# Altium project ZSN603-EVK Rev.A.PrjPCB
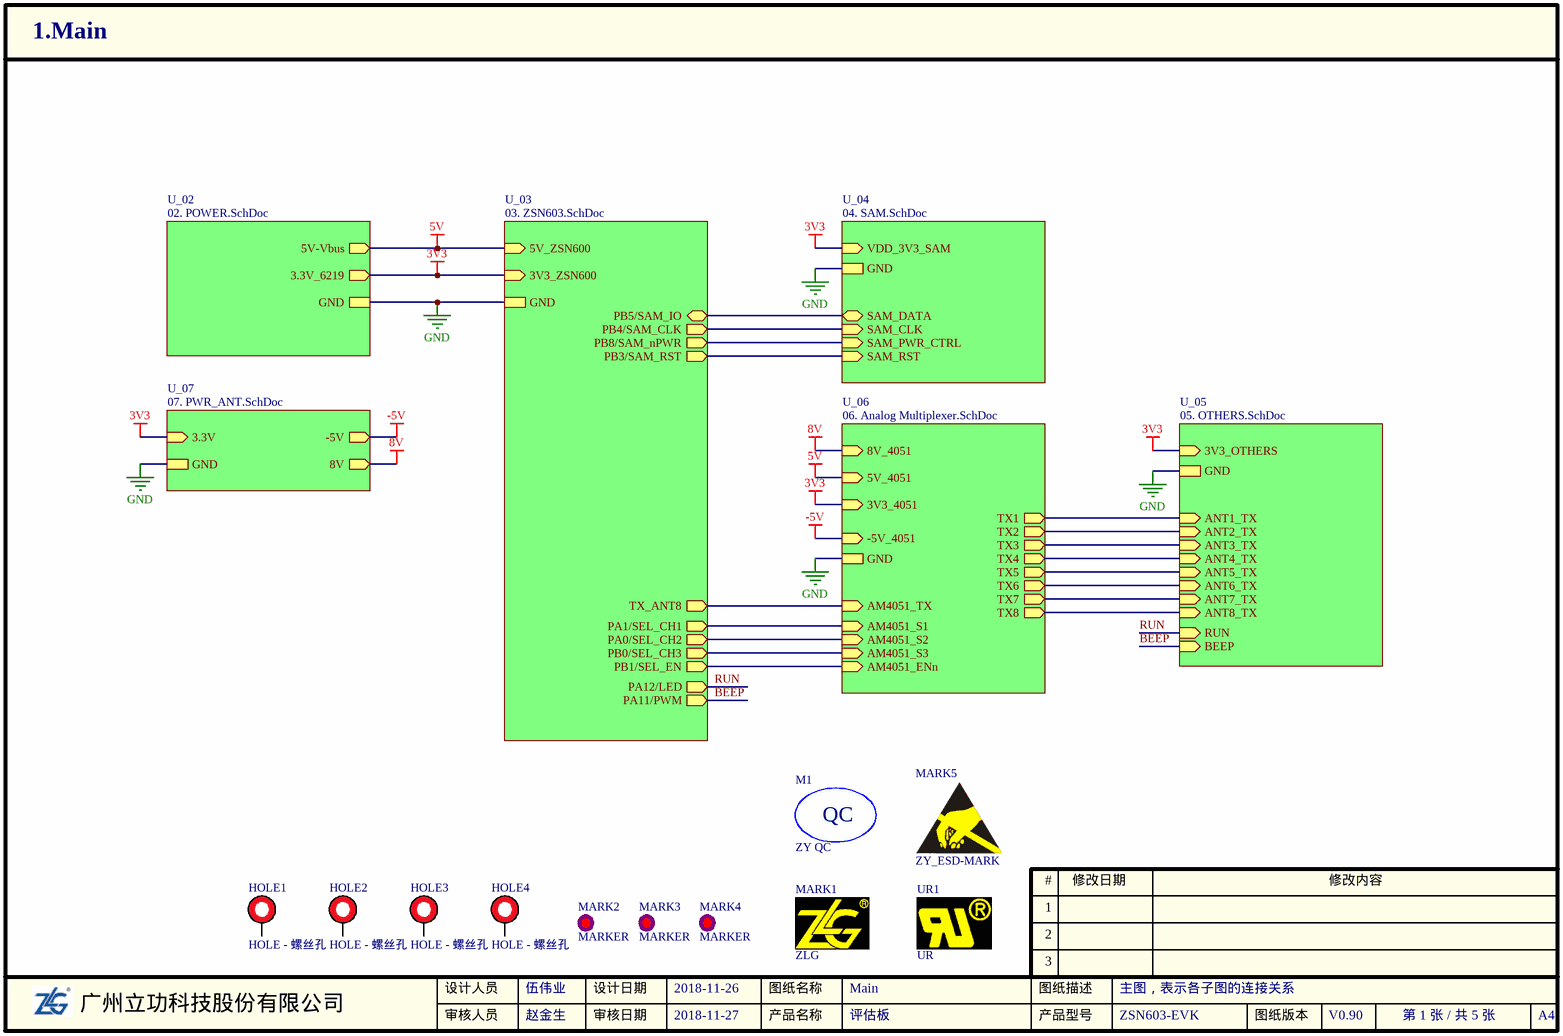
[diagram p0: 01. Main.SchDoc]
productName: 评估板; productModel: ZSN603-EVK
7 sheets, 139 parts. Net scope: hierarchical (ports join the sheet entries above them; power ports are global).
Board file: ZSN603-EVK Rev.A.PcbDoc
Sheets:
  01. Main.SchDoc
    U_02 = 02. POWER.SchDoc
    U_03 = 03. ZSN603.SchDoc
    U_04 = 04. SAM.SchDoc
    U_05 = 05. OTHERS.SchDoc
    U_06 = 06. Analog Multiplexer.SchDoc
    U_07 = 07. PWR_ANT.SchDoc

## Sheet 01. Main.SchDoc
size A4; CheckedBy: 赵金生; Author: 伍伟业; CompanyName: 广州周立功单片机科技有限公司; DocumentNumber: 1; SheetNumber: 1; SheetTotal: 5; PageSetup: Record=PageOptions¦CenterHorizontal=True¦CenterVertical=True¦PrintScale=1.00¦XCorrection=1.00¦YCorrection=1.00¦PrintKind=0¦BorderSize=5000000¦LeftOffset=0¦BottomOffset=0¦Orientation=2¦PaperLength=1000¦PaperWidth=1000¦Scale=100¦PaperSource=7¦PrintQuality=600¦MediaType=1¦DitherType=10¦PaperKind=A4¦PrintScaleMode=1; DesignDate: 2018-11-26; CheckDate: 2018-11-27; SheetName: Main; SheetVersion: V0.90; SheetDescription: 主图，表示各子图的连接关系

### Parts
HOLE1  HOLE - 螺丝孔  [HOLE-3.2 - Screw]  (no BOM)
HOLE2  HOLE - 螺丝孔  [HOLE-3.2 - Screw]  (no BOM)
HOLE3  HOLE - 螺丝孔  [HOLE-3.2 - Screw]  (no BOM)
HOLE4  HOLE - 螺丝孔  [HOLE-3.2 - Screw]  (no BOM)
M1  ZY QC  [ZY_QC]  (no BOM)
MARK1  ZLG  [ZLG1.0]  (no BOM)
MARK2  MARKER  [MARKER-C-1.0M]  (no BOM)
MARK3  MARKER  [MARKER-C-1.0M]  (no BOM)
MARK4  MARKER  [MARKER-C-1.0M]  (no BOM)
MARK5  ZY_ESD-MARK  [ZY_ESD-7]  (no BOM)
UR1  UR  [ZY_UR-3X2]  (no BOM)

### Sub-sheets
U_02 = 02. POWER.SchDoc: GND, 3.3V_6219 (out), 5V-Vbus (out)
U_03 = 03. ZSN603.SchDoc: GND, 3V3_ZSN600 (in), 5V_ZSN600 (in), PB3/SAM_RST (out), PB4/SAM_CLK (out), PB5/SAM_IO (bidir), PB8/SAM_nPWR (out), PA1/SEL_CH1 (out), PA0/SEL_CH2 (out), PB0/SEL_CH3 (out), PB1/SEL_EN (out), PA12/LED (out), PA11/PWM (out), TX_ANT8 (out)
U_04 = 04. SAM.SchDoc: SAM_CLK (in), SAM_DATA (bidir), SAM_RST (in), SAM_PWR_CTRL (in), VDD_3V3_SAM (in), GND
U_05 = 05. OTHERS.SchDoc: GND, 3V3_OTHERS (in), RUN (in), BEEP (in), ANT1_TX (in), ANT2_TX (in), ANT3_TX (in), ANT4_TX (in), ANT5_TX (in), ANT6_TX (in), ANT7_TX (in), ANT8_TX (in)
U_06 = 06. Analog Multiplexer.SchDoc: AM4051_S2 (in), AM4051_S1 (in), AM4051_S3 (in), GND, 8V_4051 (in), -5V_4051 (in), AM4051_ENn (in), AM4051_TX (in), TX1 (out), TX2 (out), TX3 (out), TX4 (out), TX5 (out), TX6 (out), TX7 (out), TX8 (out), 3V3_4051 (in), 5V_4051 (in)
U_07 = 07. PWR_ANT.SchDoc: -5V (out), 3.3V (in), GND, 8V (out)

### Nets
3V3: sheet U_02/3.3V_6219, sheet U_03/3V3_ZSN600, sheet U_04/VDD_3V3_SAM, sheet U_05/3V3_OTHERS, sheet U_06/3V3_4051, sheet U_07/3.3V  [project net 3.3V]
5V: sheet U_02/5V-Vbus, sheet U_03/5V_ZSN600, sheet U_06/5V_4051
8V: sheet U_06/8V_4051, sheet U_07/8V
-5V: sheet U_06/-5V_4051, sheet U_07/-5V
GND: sheet U_02/GND, sheet U_03/GND, sheet U_04/GND, sheet U_05/GND, sheet U_06/GND, sheet U_07/GND
AM4051_ENn: sheet U_03/PB1/SEL_EN, sheet U_06/AM4051_ENn
AM4051_S1: sheet U_03/PA1/SEL_CH1, sheet U_06/AM4051_S1
AM4051_S2: sheet U_03/PA0/SEL_CH2, sheet U_06/AM4051_S2
AM4051_S3: sheet U_03/PB0/SEL_CH3, sheet U_06/AM4051_S3
AM4051_TX: sheet U_03/TX_ANT8, sheet U_06/AM4051_TX
ANT1_TX: sheet U_05/ANT1_TX, sheet U_06/TX1
ANT2_TX: sheet U_05/ANT2_TX, sheet U_06/TX2
ANT3_TX: sheet U_05/ANT3_TX, sheet U_06/TX3
ANT4_TX: sheet U_05/ANT4_TX, sheet U_06/TX4
ANT5_TX: sheet U_05/ANT5_TX, sheet U_06/TX5
ANT6_TX: sheet U_05/ANT6_TX, sheet U_06/TX6
ANT7_TX: sheet U_05/ANT7_TX, sheet U_06/TX7
ANT8_TX: sheet U_05/ANT8_TX, sheet U_06/TX8
BEEP: sheet U_03/PA11/PWM, sheet U_05/BEEP
PB3/SAM_RST: sheet U_03/PB3/SAM_RST, sheet U_04/SAM_RST
PB4/SAM_CLK: sheet U_03/PB4/SAM_CLK, sheet U_04/SAM_CLK
PB5/SAM_IO: sheet U_03/PB5/SAM_IO, sheet U_04/SAM_DATA
PB8/SAM_nPWR: sheet U_03/PB8/SAM_nPWR, sheet U_04/SAM_PWR_CTRL
RUN: sheet U_03/PA12/LED, sheet U_05/RUN  [project net PA12/LED]

Not connected (* = marked no-connect by the designer): HOLE1 1; HOLE2 1; HOLE3 1; HOLE4 1; MARK2 0; MARK3 0; MARK4 0

## Sheet 02. POWER.SchDoc
size A4; CheckedBy: 赵金生; Author: 伍伟业; CompanyName: 广州周立功单片机科技有限公司; DocumentNumber: 2; SheetNumber: 2; SheetTotal: 5; PageSetup: Record=PageOptions|CenterHorizontal=True|CenterVertical=True|PrintScale=1.00|XCorrection=1.00|YCorrection=1.00|PrintKind=0|BorderSize=5000000|LeftOffset=0|BottomOffset=0|Orientation=2|PaperLength=1000|PaperWidth=1000|Scale=100|PaperSource=7|PrintQuality=600|MediaType=1|DitherType=10|PaperKind=A4|PrintScaleMode=1; DesignDate: 2018-11-26; CheckDate: 2018-11-27; SheetName: POWER; SheetVersion: V0.90; SheetDescription: 评估板电源
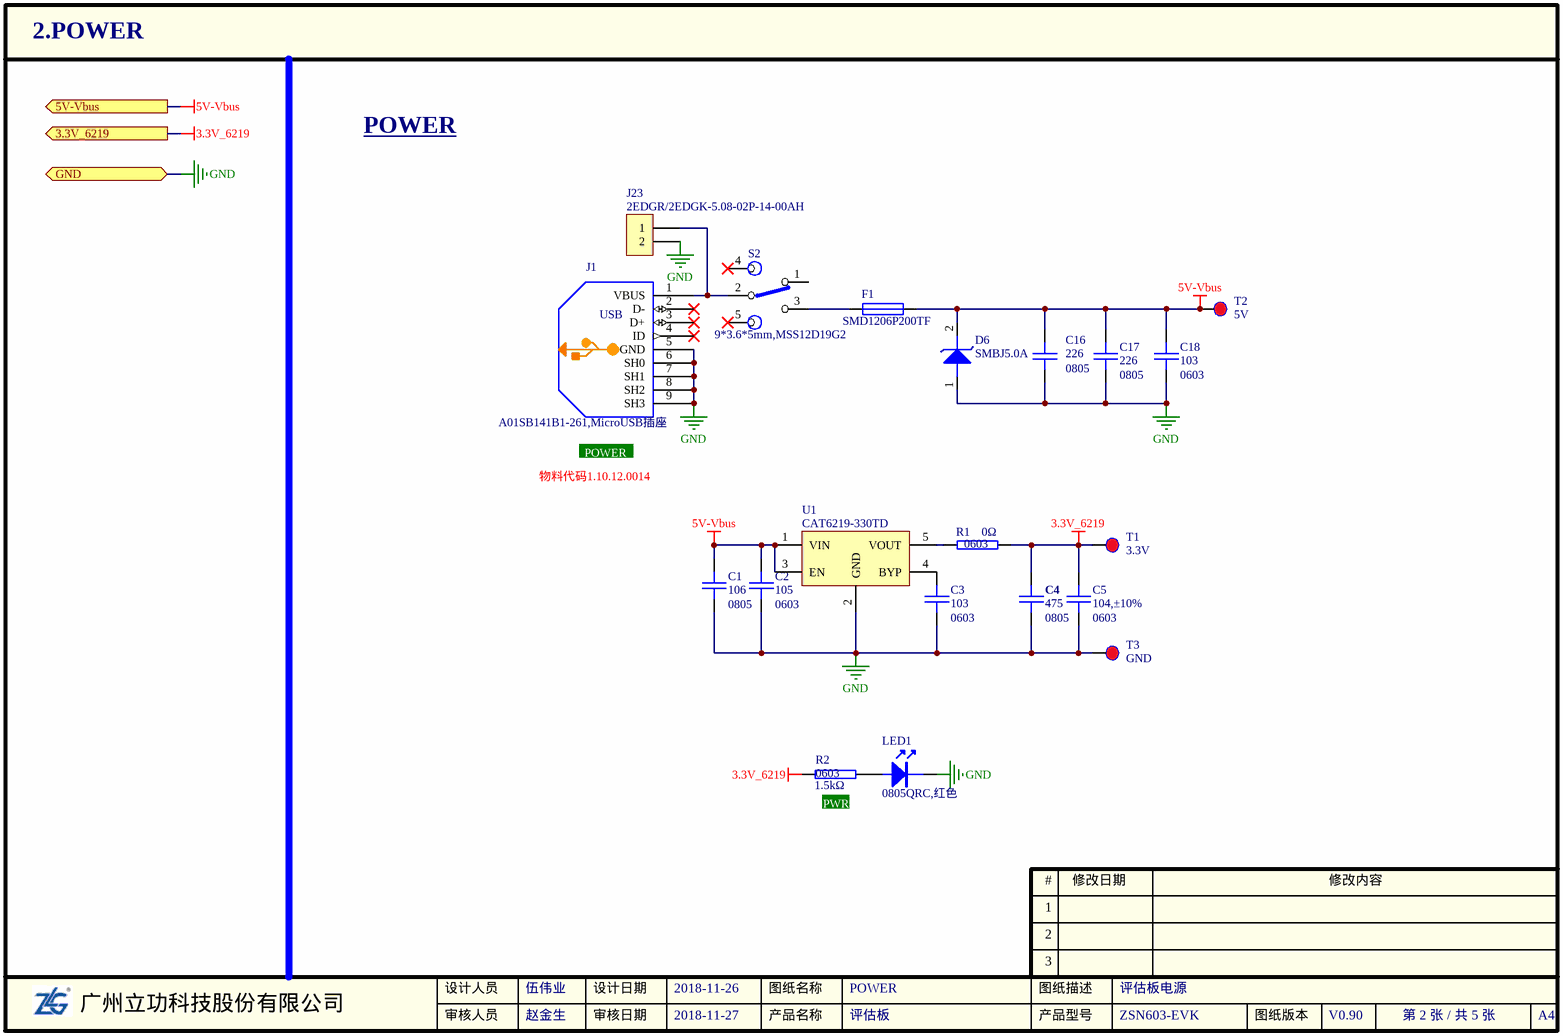
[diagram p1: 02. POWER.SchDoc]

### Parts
C1  封装: 0805  [0805C]  (hidden comment: 106)
C2  封装: 0603  [0603C]  (hidden comment: 105)
C3  封装: 0603  [0603C]  (hidden comment: 103)
C4  封装: 0805  [0805C]  (hidden comment: 475)
C5  封装: 0603  [0603C]  (hidden comment: 104,±10%)
C16  封装: 0805  [0805C]  (hidden comment: 226)
C17  封装: 0805  [0805C]  (hidden comment: 226)
C18  封装: 0603  [0603C]  (hidden comment: 103)
D6  SMBJ5.0A  [SOD-1812D]
F1  SMD1206P200TF  [FUSE320X165X160]
J1  A01SB141B1-261,MicroUSB插座  [MICROUSB-5S]
J23  2EDGR/2EDGK-5.08-02P-14-00AH  [CON508P1210W160D445S-2RA]
LED1  0805QRC,红色  [LED-0805]
R1  封装: 0603  [0603R]  (hidden comment: 0Ω)
R2  封装: 0603  [0603R]  (hidden comment: 1.5kΩ)
S2  9*3.6*5mm,MSS12D19G2  [MSS12D19G2]
T1  3.3V  [PAD-25/40]  (no BOM)
T2  5V  [PAD-25/40]  (no BOM)
T3  GND  [PAD-25/40]  (no BOM)
U1  CAT6219-330TD  [SOT-23-5]

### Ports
3.3V_6219 (out), 5V-Vbus (out), GND

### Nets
3.3V_6219: C4.1 C5.1 R1.2 R2.1 T1.1 ; port 3.3V_6219  [project net 3.3V]
5V-Vbus: C1.1 C2.1 C16.1 C17.1 C18.1 D6.2 F1.2 T2.1 U1.1(VIN) U1.3(EN) ; port 5V-Vbus  [project net 5V]
GND: C1.2 C2.2 C3.2 C4.2 C5.2 C16.2 C17.2 C18.2 D6.1 J1.5(GND) J1.6(SH0) J1.7(SH1) J1.8(SH2) J1.9(SH3) J23.2 LED1.2 T3.1 U1.2(GND) ; port GND
NetC3_1: C3.1 U1.4(BYP)
NetF1_1: F1.1 S2.3(NO)
NetJ1_1: J1.1(VBUS) J23.1 S2.2(COMMON)
NetLED1_1: LED1.1 R2.2
NetR1_1: R1.1 U1.5(VOUT)

Not connected (* = marked no-connect by the designer): J1 2(D-)* 3(D+)* 4(ID)*; S2 1(NC) 4(NO)* 5(NO)*

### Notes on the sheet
- POWER
- 物料代码1.10.12.0014
- (near J1) POWER
- (near R2) PWR

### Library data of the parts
C1 = 1.02.02.0055: 106,10μF,±10%,10V,X5R,0805,RoHS; 名称: 电容; 贴片和直插: SMT; 器件优选方案: 量产物料,优先选用; 设备封装名称: C0805_106_X5R_10V_10%
C2 = 1.02.01.0036: 105,1μF,±10%,16V,X7R,0603,*,RoHS; 名称: 电容; 设备封装名称: C0603_105_X7R_16V_10%; 厂商: TDK; 贴片和直插: SMT; 器件优选方案: 量产物料,不推荐使用
C3 = 1.02.01.0024: 103,±10%,50V,X7R,0603,*,RoHS; 名称: 电容; 设备封装名称: C0603_103_X7R_50V_10%; 厂商: muRata; 贴片和直插: SMT; 器件优选方案: 量产物料,不推荐使用
C4 = 1.02.02.0064: 475,±10%,16V,X7R,0805,RoHS; 名称: 电容; 设备封装名称: C0805_475_X7R_16V_10%; 贴片和直插: SMT; 器件优选方案: 优先选用
C5 = 1.02.01.0032: Capacitor; 名称: 电容; 设备封装名称: C0603_104_X7R_50V_10%; 厂商: muRata; 型号: 104,±10%,50V,X7R; 贴片和直插: SMT; 器件优选方案: 量产物料,优先选用
C16 C17 = 1.02.02.0059: GRM21BR60J226ME39L,226,22μF,±20%,6.3V,X5R,0805,muRata,RoHS; 名称: 电容; 设备封装名称: C0805_226_X5R_6.3V_20%; 贴片和直插: SMT; 器件优选方案: 正常状态，可以选用
C18 = 1.02.01.0024: GRM188R71H103KA01D,103,±10%,50V,X7R,0603,muRata,RoHS; 名称: 电容; 设备封装名称: C0603_103_X7R_50V_10%; 贴片和直插: SMT; 器件优选方案: 正常状态，可以选用
D6 = 1.04.03.0001: SMBJ5.0A,DO-214AA,君耀,RoHS; 名称: TVS瞬态抑制二极管; 设备封装名称: DO-214AA_SMBJ5.0A; 贴片和直插: SMT; 器件优选方案: 正常状态，可以选用
F1 = 1.06.03.0017: SMD1206P200TF,1206,Polytronics,RoHS; 名称: 保险丝; 封装: 1206; 贴片和直插: SMT; 器件优选方案: 临时/偏门物料/不主推物料，谨慎选用
J1 = 1.10.12.0014: A01SB141B1-261,MicroUSB插座,SMT,艾立信,RoHS; PCB备注: 141030lmd; 器件优选方案: 正常状态，可以选用
J23 = 1.10.06.0027: 2EDGR/2EDGK-5.08-02P-14-00AH,DEGSON,RoHS; 名称: 端子; 贴片和直插: THT; PCB备注: xhm-lq-wyy-150126; 器件优选方案: 正常状态，可以选用
LED1 = 1.04.05.0001: 0805QRC,红色,0805,RoHS; 名称: 发光二极管; 封装: 0805; 设备封装名称: LED0805-RED; 贴片和直插: SMT; 器件优选方案: 正常状态，可以选用
R1 = 1.01.01.0001: 名称: 电阻; 设备封装名称: R0603_0R; 厂商: Ralec; 贴片和直插: SMT; 器件优选方案: 状态正常
R2 = 1.01.01.0037: 1.5KΩ,0603,*,RoHS; 名称: 电阻; 设备封装名称: R0603_1.5K; 厂商: Ralec; 贴片和直插: SMT; 器件优选方案: 状态正常
S2 = 1.09.07.0029: 9*3.6*5mm,MSS12D19G2,东昇,RoHS; 名称: 拨动开关; 贴片和直插: THT; PCB备注: 170616 ZJY; 器件优选方案: 正常状态，可以选用
T1-T3 = TEST-DOT
U1 = 1.05.10.0321: CAT6219-330TD,TSOT-23-5,ON,RoHS; 名称: 集成电路; 设备封装名称: TSOT-23-5_CAT6219-330TD-GT3; 贴片和直插: SMT; 器件优选方案: 量产物料,优先选用

## Sheet 03. ZSN603.SchDoc
size A3; CheckedBy: 赵金生; Author: 伍伟业; CompanyName: 广州周立功单片机科技有限公司; DocumentNumber: 3; SheetNumber: 3; SheetTotal: 5; PageSetup: Record=PageOptions¦CenterHorizontal=True¦CenterVertical=True¦PrintScale=1.00¦XCorrection=1.00¦YCorrection=1.00¦PrintKind=0¦BorderSize=5000000¦LeftOffset=0¦BottomOffset=0¦Orientation=2¦PaperLength=1000¦PaperWidth=1000¦Scale=100¦PaperSource=7¦PrintQuality=600¦MediaType=1¦DitherType=10¦PaperKind=A4¦PrintScaleMode=1; DesignDate: 2018-11-26; CheckDate: 2018-11-27; SheetName: ZSN603; SheetVersion: V0.90; SheetDescription: ZSN603最小系统及信号端口
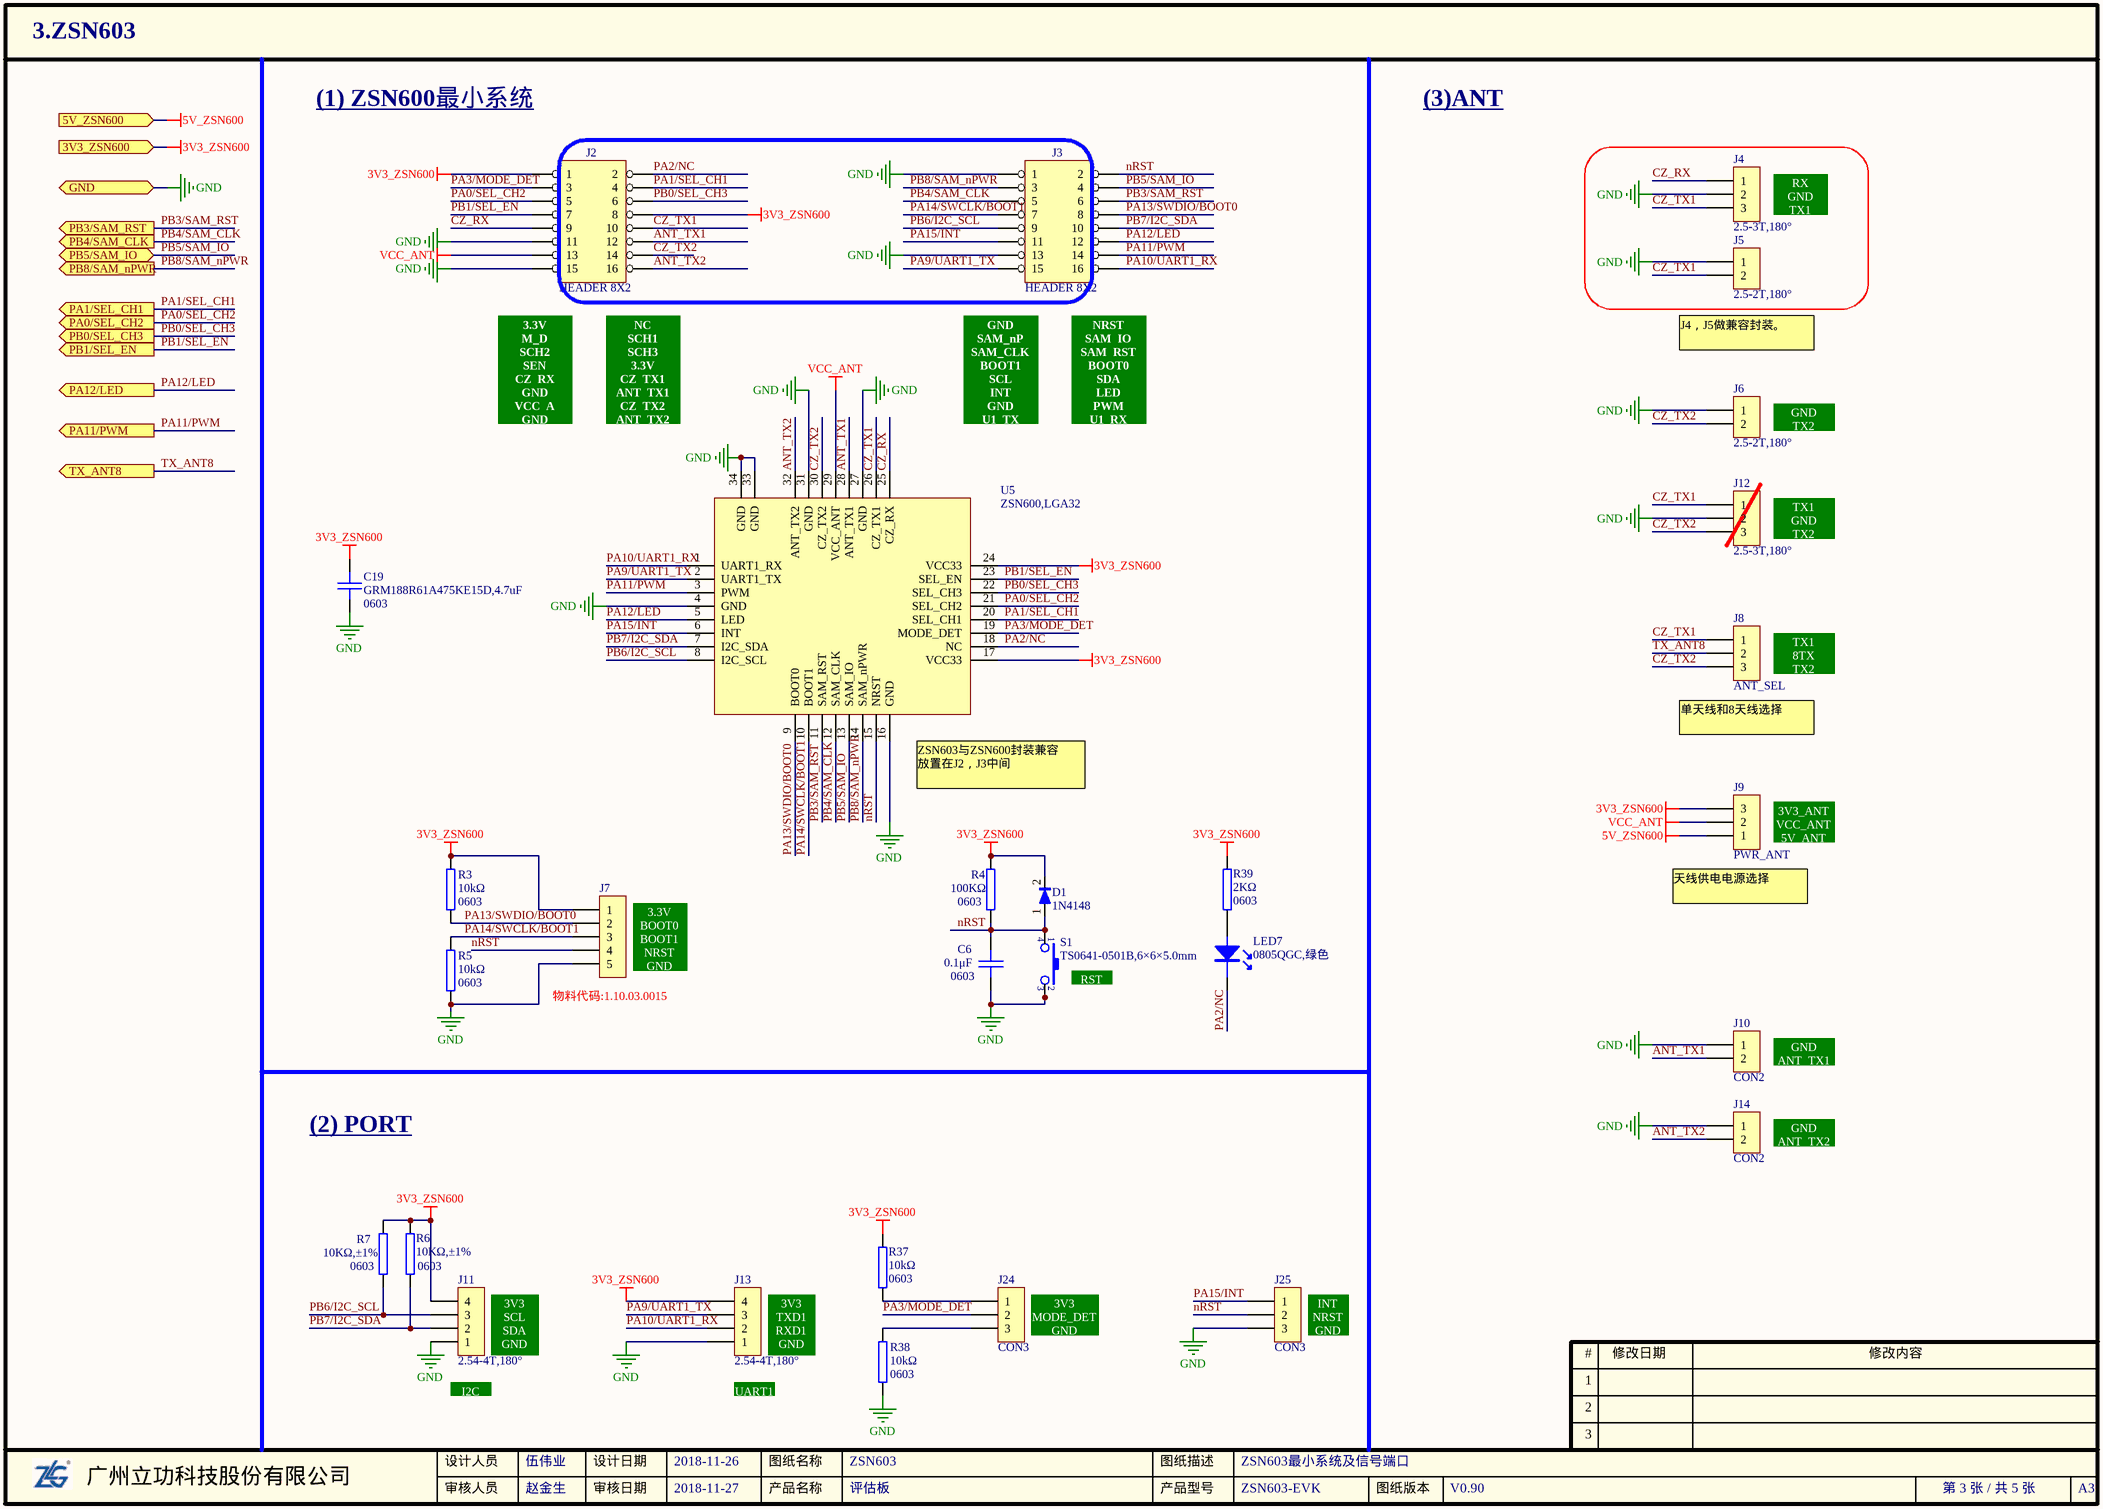
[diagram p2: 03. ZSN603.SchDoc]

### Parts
C6  封装: 0603  [0603C]  (hidden comment: 0.1μF)
C19  封装: 0603  [0603C]  (hidden comment: GRM188R61A475KE15D,4.7uF)
D1  1N4148  [SOD-323]
J2  HEADER 8X2  [IDC-16-2.54]
J3  HEADER 8X2  [IDC-16-2.54]
J4  2.5-3T,180°  [CON250P580W100D50S-3DIP]
J5  2.5-2T,180°  [CON250P580W100D50S-2DIP]
J6  2.5-2T,180°  [CON250P580W100D50S-2DIP]
J7  (no value)  [SIP-5-2.54-6.0-R90]
J8  ANT_SEL  [SIP-3-2.54]
J9  PWR_ANT  [SIP-3-2.54]
J10  CON2  [SIP-2-2.54]
J11  2.54-4T,180°  [CON250P580W100D50S-4DIP]
J12  2.5-3T,180°  [CON250P580W100D50S-3DIP]
J13  2.54-4T,180°  [CON250P580W100D50S-4DIP]
J14  CON2  [SIP-2-2.54]
J24  CON3  [SIP-3-2.54]
J25  CON3  [SIP-3-2.54]
LED7  0805QGC,绿色  [LED-0805]
R3  封装: 0603  [0603R]  (hidden comment: 10kΩ)
R4  封装: 0603  [0603R]  (hidden comment: 100KΩ)
R5  封装: 0603  [0603R]  (hidden comment: 10kΩ)
R6  封装: 0603  [0603R]  (hidden comment: 10KΩ,±1%)
R7  封装: 0603  [0603R]  (hidden comment: 10KΩ,±1%)
R37  封装: 0603  [0603R]  (hidden comment: 10kΩ)
R38  封装: 0603  [0603R]  (hidden comment: 10kΩ)
R39  封装: 0603  [0603R]  (hidden comment: 2KΩ)
S1  TS0641-0501B,6×6×5.0mm  [KEY-6S]
U5  ZSN600,LGA32  [ZSN600]

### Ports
3V3_ZSN600 (in), 5V_ZSN600 (in), GND, PA0/SEL_CH2 (out), PA1/SEL_CH1 (out), PA11/PWM (out), PA12/LED (out), PB0/SEL_CH3 (out), PB1/SEL_EN (out), PB3/SAM_RST (out), PB4/SAM_CLK (out), PB5/SAM_IO (bidir), PB8/SAM_nPWR (out), TX_ANT8 (out)

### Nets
3V3_ZSN600: C19.1 D1.2 J2.1 J2.8 J7.1 J9.3 J11.4 J13.4 R3.2 R4.2 R6.2 R7.2 R37.1 R39.2 U5.17(VCC33) U5.24(VCC33) ; port 3V3_ZSN600  [project net 3.3V]
5V_ZSN600: J9.1 ; port 5V_ZSN600  [project net 5V]
GND: C6.2 C19.2 J2.11 J2.15 J3.1 J3.13 J4.2 J5.1 J6.1 J7.5 J10.1 J11.1 J12.2 J13.1 J14.1 J25.3 R5.1 R38.1 S1.2 S1.3 U5.4(GND) U5.16(GND) U5.27(GND) U5.31(GND) U5.33(GND) U5.34(GND) ; port GND
VCC_ANT: J2.13 J9.2 U5.29(VCC_ANT)
ANT_TX1: J2.12 J10.2 U5.28(ANT_TX1)
ANT_TX2: J2.16 J14.2 U5.32(ANT_TX2)
CZ_RX: J2.9 J4.1 U5.25(CZ_RX)
CZ_TX1: J2.10 J4.3 J5.2 J8.1 J12.1 U5.26(CZ_TX1)
CZ_TX2: J2.14 J6.2 J8.3 J12.3 U5.30(CZ_TX2)
nRST: C6.1 D1.1 J3.2 J7.4 J25.2 R4.1 S1.1 S1.4 U5.15(NRST)
PA0/SEL_CH2: J2.5 U5.21(SEL_CH2) ; port PA0/SEL_CH2  [project net AM4051_S2]
PA1/SEL_CH1: J2.4 U5.20(SEL_CH1) ; port PA1/SEL_CH1  [project net AM4051_S1]
PA2/NC: J2.2 LED7.2 U5.18(NC)
PA3/MODE_DET: J2.3 J24.2 U5.19(MODE_DET)
PA9/UART1_TX: J3.15 J13.3 U5.2(UART1_TX)
PA10/UART1_RX: J3.16 J13.2 U5.1(UART1_RX)
PA11/PWM: J3.14 U5.3(PWM) ; port PA11/PWM  [project net BEEP]
PA12/LED: J3.12 U5.5(LED) ; port PA12/LED
PA13/SWDIO/BOOT0: J3.8 J7.2 R3.1 U5.9(BOOT0)
PA14/SWCLK/BOOT1: J3.7 J7.3 R5.2 U5.10(BOOT1)
PA15/INT: J3.11 J25.1 U5.6(INT)
PB0/SEL_CH3: J2.6 U5.22(SEL_CH3) ; port PB0/SEL_CH3  [project net AM4051_S3]
PB1/SEL_EN: J2.7 U5.23(SEL_EN) ; port PB1/SEL_EN  [project net AM4051_ENn]
PB3/SAM_RST: J3.6 U5.11(SAM_RST) ; port PB3/SAM_RST
PB4/SAM_CLK: J3.5 U5.12(SAM_CLK) ; port PB4/SAM_CLK
PB5/SAM_IO: J3.4 U5.13(SAM_IO) ; port PB5/SAM_IO
PB6/I2C_SCL: J3.9 J11.3 R7.1 U5.8(I2C_SCL)
PB7/I2C_SDA: J3.10 J11.2 R6.1 U5.7(I2C_SDA)
PB8/SAM_nPWR: J3.3 U5.14(SAM_nPWR) ; port PB8/SAM_nPWR
TX_ANT8: J8.2 ; port TX_ANT8  [project net AM4051_TX]
NetJ24_1: J24.1 R37.2
NetJ24_3: J24.3 R38.2
NetLED7_1: LED7.1 R39.1

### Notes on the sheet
- (1) ZSN600最小系统
- (3)ANT
- RX
  GND
  TX1
- CZ_RX
- SEN
- SCH2
- M_D
- (near J2) 3.3V
- (near J2) NC
- SCH1
- SCH3
- 3.3V
- CZ_TX1
- SCL
- BOOT1
- SAM_CLK
- SAM_nP
- (near J3) GND
- (near J3) NRST
- SAM_IO
- SAM_RST
- BOOT0
- SDA
- J4，J5做兼容封装。
- VCC_A
- GND
- ANT_TX1
- CZ_TX2
- ANT_TX2
- U1_TX
- INT
- LED
- PWM
- U1_RX
- (near J6) GND
  TX2
- (near J12) TX1
  GND
  TX2
- (near J8) TX1
  8TX
  TX2
- (near U5) ZSN603与ZSN600封装兼容
  放置在J2，J3中间
- (near J8) 单天线和8天线选择
- (near J9) 3V3_ANT
  VCC_ANT
  5V_ANT
- (near J9) 天线供电电源选择
- (near J7) 3.3V
  BOOT0
  BOOT1
  NRST
  GND
- (near S1) RST
- (near J7) 物料代码:1.10.03.0015
- (near J10) GND
  ANT_TX1
- (2) PORT
- (near J14) GND
  ANT_TX2
- (near J11) I2C
- (near J11) 3V3
  SCL
  SDA
  GND
- (near J13) UART1
- (near J13) 3V3
  TXD1
  RXD1
  GND
- (near J24) 3V3
  MODE_DET
  GND
- (near J25) INT
  NRST
  GND

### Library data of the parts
C6 = 1.02.01.0032: GRM188R71H104KA93D,104,±10%,50V,X7R,0603,muRata,RoHS; 名称: 电容; 贴片和直插: SMT; 器件优选方案: 临时/偏门物料/不主推物料，谨慎选用; 设备封装名称: C0603_104_X7R_50V_10%
C19 = 1.02.01.0080: GRM188R61A475KE15D,4.7uF,±10%,10V,X5R,0603,muRata,RoHS; 名称: 电容; 贴片和直插: SMT; PCB备注: 160602yjh; 器件优选方案: 正常状态，可以选用
D1 = 1.04.07.0027: 1N4148,SOD-323,长电,RoHS; 名称: 二极管; 设备封装名称: SOD-323_1N4148; 贴片和直插: SMT; 器件优选方案: 正常状态，可以选用
J4 J12 = 1.10.06.0010: 2.5-3T,180°,PA46本色,WF2501-WSH03T02,WCON,RoHS; 名称: 插座; 贴片和直插: THT; PCB备注: xhm-lq-wyy-150123 / 150918mxz; 器件优选方案: 正常状态，可以选用
J5 J6 = 1.10.06.0009: 2.5-2T,180°,PA46本色,WF2501-WSH02T02,WCON,RoHS; 名称: 插座; 贴片和直插: THT; PCB备注: xhm-lq-wyy-150123 / 150918mxz; 器件优选方案: 正常状态，可以选用
J7 = CON5: Connector
J8 J9 J24 J25 = CON3: Connector
J10 J14 = CON2: Connector
J11 J13 = 1.10.06.0011: 2.54-4T,180°,,*; 名称: 插座; 贴片和直插: THT; PCB备注: xhm-lq-wyy-150123 / 150918mxz; 器件优选方案: 正常状态，可以选用
LED7 = 1.04.05.0002: 0805QGC,绿色,0805,RoHS; 名称: 发光二极管; 封装: 0805; 设备封装名称: LED0805-GREEN; 贴片和直插: SMT; 器件优选方案: 正常状态，可以选用
R3 R5 R37 R38 = 1.01.01.0052: 10KΩ,±1%,0603,*,RoHS; 名称: 电阻; 设备封装名称: R0603_10K_1%; 厂商: Ralec; 贴片和直插: SMT
R4 = 1.01.01.0062: 100KΩ,0603,*,RoHS; 名称: 电阻; 设备封装名称: R0603_100K; 厂商: Ralec; 贴片和直插: SMT; 器件优选方案: 正常状态，可以选用
R6 R7 = 1.01.01.0052: 10KΩ,±1%,0603,*,RoHS; 名称: 电阻; 设备封装名称: R0603_10K_1%; 厂商: Ralec; 贴片和直插: SMT; 器件优选方案: 正常状态，可以选用
R39 = 1.01.01.0038: 2KΩ,0603,*,RoHS; 名称: 电阻; 设备封装名称: R0603_2K; 厂商: Ralec; 贴片和直插: SMT; 器件优选方案: 正常状态，可以选用
S1 = 1.09.01.0003: TS0641-0501B,6×6×5.0mm,黑色,SMD,卷带装,RoHS; 名称: 轻触开关; 贴片和直插: SMT; 器件优选方案: 正常状态，可以选用
U5 = 08.08.00853: ZSN600,LGA32,ZLG; 名称: 集成电路; 封装: LGA-32; 贴片和直插: SMT; PCB备注: 190305lmd; 器件优选方案: 待导入物料

## Sheet 04. SAM.SchDoc
size A4; CheckedBy: 赵金生; Author: 伍伟业; CompanyName: 广州周立功单片机科技有限公司; DocumentNumber: 4; SheetNumber: 4; SheetTotal: 5; PageSetup: Record=PageOptions¦CenterHorizontal=True¦CenterVertical=True¦PrintScale=1.00¦XCorrection=1.00¦YCorrection=1.00¦PrintKind=0¦BorderSize=5000000¦LeftOffset=0¦BottomOffset=0¦Orientation=2¦PaperLength=1000¦PaperWidth=1000¦Scale=100¦PaperSource=7¦PrintQuality=600¦MediaType=1¦DitherType=10¦PaperKind=A4¦PrintScaleMode=1; DesignDate: 2018-11-26; CheckDate: 2018-11-27; SheetName: SAM; SheetVersion: V0.90; SheetDescription: SAM卡电路
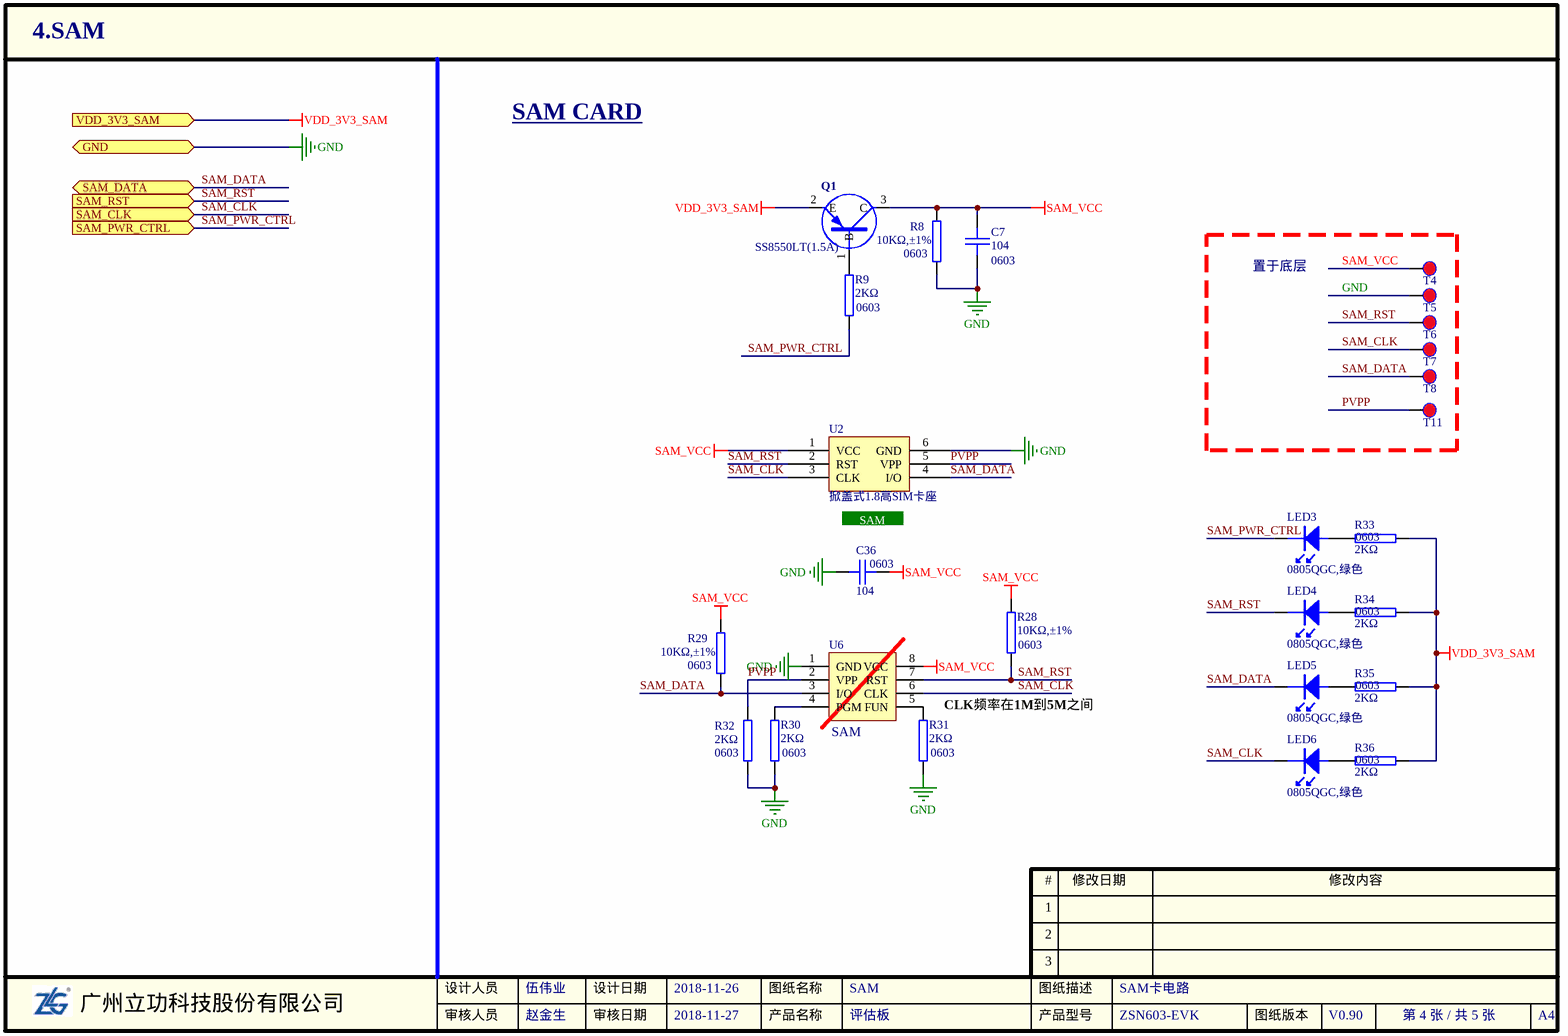
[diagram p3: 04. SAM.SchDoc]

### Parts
C7  封装: 0603  [0603C]  (hidden comment: 104)
C36  封装: 0603  [0603C]  (hidden comment: 104)
LED3  0805QGC,绿色  [LED-0805]
LED4  0805QGC,绿色  [LED-0805]
LED5  0805QGC,绿色  [LED-0805]
LED6  0805QGC,绿色  [LED-0805]
Q1  value SS8550LT(1.5A)  [SOT-23]  (hidden comment: PNP-1)
R8  封装: 0603  [0603R]  (hidden comment: 10KΩ,±1%)
R9  封装: 0603  [0603R]  (hidden comment: 2KΩ)
R28  封装: 0603  [0603R]  (hidden comment: 10KΩ,±1%)
R29  封装: 0603  [0603R]  (hidden comment: 10KΩ,±1%)
R30  封装: 0603  [0603R]  (hidden comment: 2KΩ)
R31  封装: 0603  [0603R]  (hidden comment: 2KΩ)
R32  封装: 0603  [0603R]  (hidden comment: 2KΩ)
R33  封装: 0603  [0603R]  (hidden comment: 2KΩ)
R34  封装: 0603  [0603R]  (hidden comment: 2KΩ)
R35  封装: 0603  [0603R]  (hidden comment: 2KΩ)
R36  封装: 0603  [0603R]  (hidden comment: 2KΩ)
T4  TEST-DOT  [PAD-40]  (value not drawn)  (no BOM)
T5  TEST-DOT  [PAD-40]  (value not drawn)  (no BOM)
T6  TEST-DOT  [PAD-40]  (value not drawn)  (no BOM)
T7  TEST-DOT  [PAD-40]  (value not drawn)  (no BOM)
T8  TEST-DOT  [PAD-40]  (value not drawn)  (no BOM)
T11  TEST-DOT  [PAD-40]  (value not drawn)  (no BOM)
U2  掀盖式1.8高SIM卡座  [SIM-CARD-24.65X17.65-6P]
U6  HEADER 4X2R  [DIP762W62P254L1016H500Q8P]  (value not drawn)

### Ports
GND, SAM_CLK (in), SAM_DATA (bidir), SAM_PWR_CTRL (in), SAM_RST (in), VDD_3V3_SAM (in)

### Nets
GND: C7.2 C36.2 R8.2 R30.1 R31.1 R32.1 T5.1 U2.6(GND) U6.1(GND) ; port GND
SAM_VCC: C7.1 C36.1 Q1.3(C) R8.1 R28.2 R29.2 T4.1 U2.1(VCC) U6.8(VCC)
VDD_3V3_SAM: Q1.2(E) R33.2 R34.2 R35.2 R36.2 ; port VDD_3V3_SAM  [project net 3.3V]
PVPP: R32.2 T11.1 U2.5(VPP) U6.2(VPP)
SAM_CLK: LED6.2 T7.1 U2.3(CLK) U6.6(CLK) ; port SAM_CLK  [project net PB4/SAM_CLK]
SAM_DATA: LED5.2 R29.1 T8.1 U2.4(I/O) U6.3(I/O) ; port SAM_DATA  [project net PB5/SAM_IO]
SAM_PWR_CTRL: LED3.2 R9.1 ; port SAM_PWR_CTRL  [project net PB8/SAM_nPWR]
SAM_RST: LED4.2 R28.1 T6.1 U2.2(RST) U6.7(RST) ; port SAM_RST  [project net PB3/SAM_RST]
NetLED3_1: LED3.1 R33.1
NetLED4_1: LED4.1 R34.1
NetLED5_1: LED5.1 R35.1
NetLED6_1: LED6.1 R36.1
NetQ1_1: Q1.1(B) R9.2
NetR30_2: R30.2 U6.4(PGM)
NetR31_2: R31.2 U6.5(FUN)

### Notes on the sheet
- SAM CARD
- 置于底层
- SAM
- (near R31) CLK频率在1M到5M之间
- (near U6) SAM

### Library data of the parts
C7 C36 = 1.02.01.0032: GRM188R71H104KA93D,104,±10%,50V,X7R,0603,muRata,RoHS; 名称: 电容; 设备封装名称: C0603_104_X7R_50V_10%; 贴片和直插: SMT; 器件优选方案: 临时/偏门物料/不主推物料，谨慎选用
LED3-LED6 = 1.04.05.0002: as LED7 on sheet 03. ZSN603
Q1 = 1.04.09.0002: SS8550LT(1.5A),SOT-23,江苏长电,RoHS; 名称: 三极管; 设备封装名称: SOT-23_SS8550LT; 贴片和直插: SMT
R8 R28 R29 = 1.01.01.0052: as R6 on sheet 03. ZSN603
R9 R30-R36 = 1.01.01.0038: as R39 on sheet 03. ZSN603
U2 = 1.10.17.0012: 名称: SIM卡座; 贴片和直插: SMT; PCB备注: 180227ZW; 器件优选方案: 正常状态，可以选用
U6 = 1.10.02.0001: DIP-8,300mil,,*; 名称: IC座; 贴片和直插: THT; PCB备注: 160128lmd

## Sheet 05. OTHERS.SchDoc
size A4; CheckedBy: 赵金生; Author: 伍伟业; CompanyName: 广州周立功单片机科技有限公司; DocumentNumber: 5; SheetNumber: 5; SheetTotal: 5; PageSetup: Record=PageOptions|CenterHorizontal=True|CenterVertical=True|PrintScale=1.00|XCorrection=1.00|YCorrection=1.00|PrintKind=0|BorderSize=5000000|LeftOffset=0|BottomOffset=0|Orientation=2|PaperLength=1000|PaperWidth=1000|Scale=100|PaperSource=7|PrintQuality=600|MediaType=1|DitherType=10|PaperKind=A4|PrintScaleMode=1; DesignDate: 2018-11-26; CheckDate: 2018-11-27; SheetName: OTHERS; SheetVersion: V0.90; SheetDescription: 指示灯和蜂鸣器电路
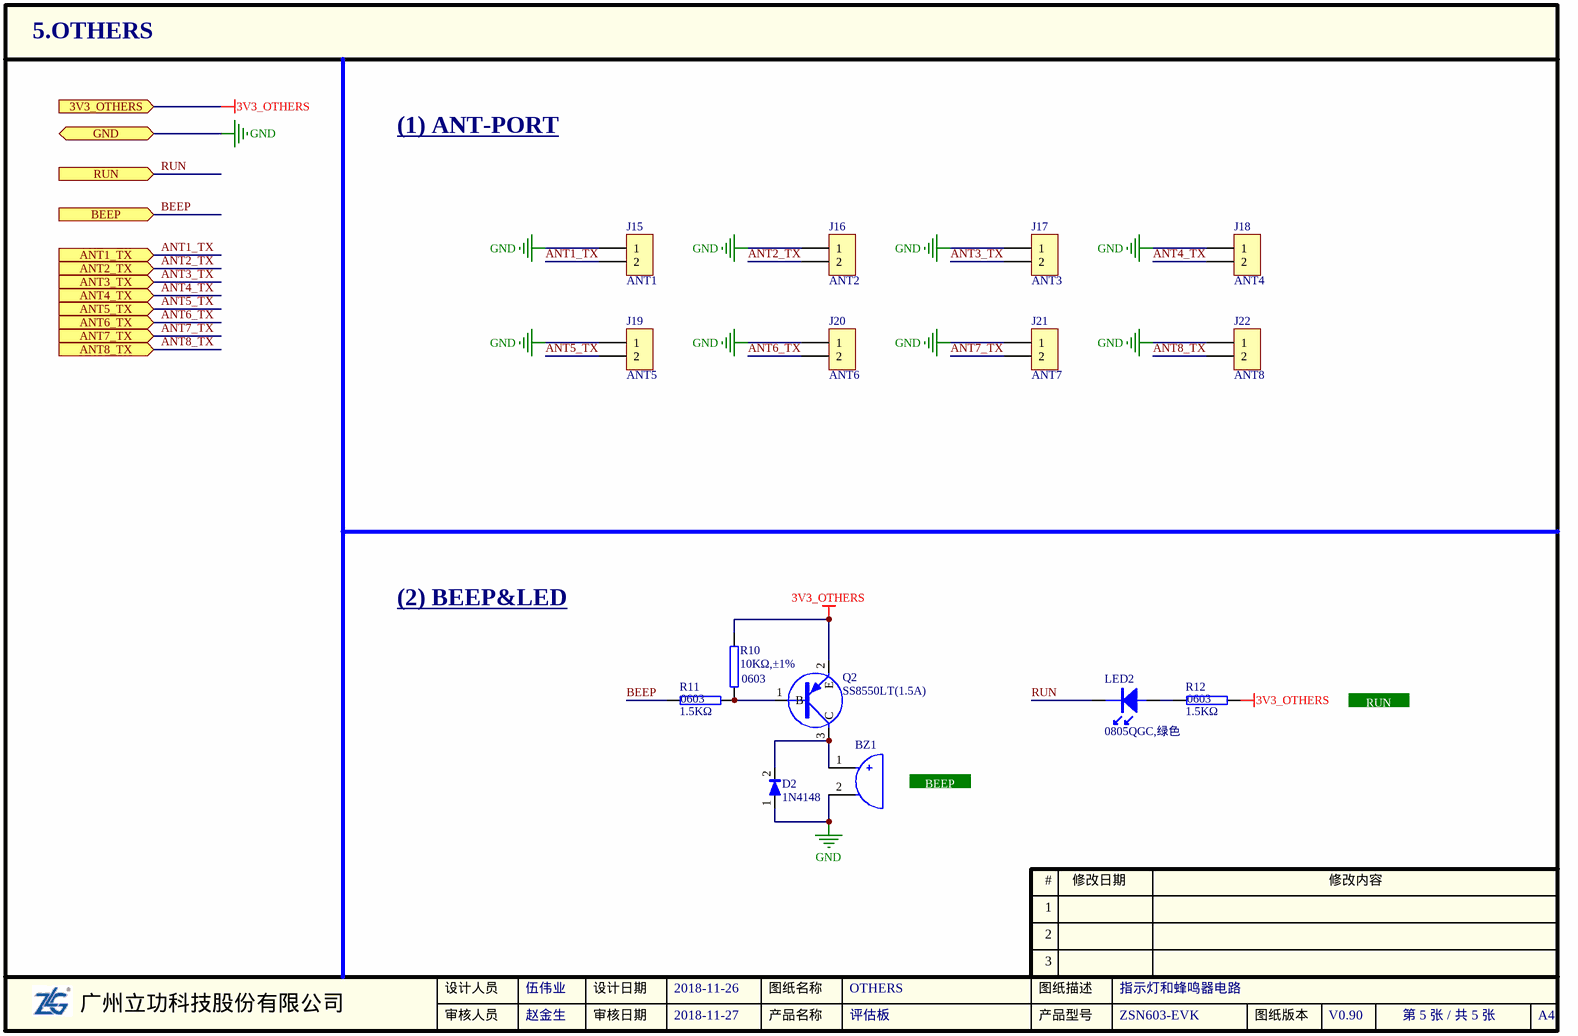
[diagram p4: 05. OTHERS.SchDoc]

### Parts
BZ1  BUZZER2  [BUZZ-4/9]  (value not drawn)
D2  value 1N4148  [SOD-323]  (hidden comment: DIODE1)
J15  ANT1  [CON250P580W100D50S-2DIP]
J16  ANT2  [CON250P580W100D50S-2DIP]
J17  ANT3  [CON250P580W100D50S-2DIP]
J18  ANT4  [CON250P580W100D50S-2DIP]
J19  ANT5  [CON250P580W100D50S-2DIP]
J20  ANT6  [CON250P580W100D50S-2DIP]
J21  ANT7  [CON250P580W100D50S-2DIP]
J22  ANT8  [CON250P580W100D50S-2DIP]
LED2  0805QGC,绿色  [LED-0805]
Q2  value SS8550LT(1.5A)  [SOT-23]  (hidden comment: PNP-1)
R10  封装: 0603  [0603R]  (hidden comment: 10KΩ,±1%)
R11  封装: 0603  [0603R]  (hidden comment: 1.5KΩ)
R12  封装: 0603  [0603R]  (hidden comment: 1.5KΩ)

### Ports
3V3_OTHERS (in), ANT1_TX (in), ANT2_TX (in), ANT3_TX (in), ANT4_TX (in), ANT5_TX (in), ANT6_TX (in), ANT7_TX (in), ANT8_TX (in), BEEP (in), GND, RUN (in)

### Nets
3V3_OTHERS: Q2.2(E) R10.2 R12.1 ; port 3V3_OTHERS  [project net 3.3V]
GND: BZ1.2(B) D2.1 J15.1 J16.1 J17.1 J18.1 J19.1 J20.1 J21.1 J22.1 ; port GND
ANT1_TX: J15.2 ; port ANT1_TX
ANT2_TX: J16.2 ; port ANT2_TX
ANT3_TX: J17.2 ; port ANT3_TX
ANT4_TX: J18.2 ; port ANT4_TX
ANT5_TX: J19.2 ; port ANT5_TX
ANT6_TX: J20.2 ; port ANT6_TX
ANT7_TX: J21.2 ; port ANT7_TX
ANT8_TX: J22.2 ; port ANT8_TX
BEEP: R11.1 ; port BEEP
RUN: LED2.2 ; port RUN  [project net PA12/LED]
NetBZ1_1: BZ1.1(A) D2.2 Q2.3(C)
NetLED2_1: LED2.1 R12.2
NetQ2_1: Q2.1(B) R10.1 R11.2

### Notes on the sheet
- (1) ANT-PORT
- (2) BEEP&LED
- RUN
- BEEP

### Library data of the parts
BZ1 = 1.06.09.0016: Buzzer有极性; Value: AS-905I-LF,无源; 名称: 讯响器; 厂商: 常州笠翔; 型号: AS-905I-LF,无源,Ф9×4.8mm; 贴片和直插: THT; PCB备注: Flq-Shcj-Twrj-150113; 器件优选方案: 量产物料,优先选用
D2 = 1.04.07.0027: 1N4148,SOD-323,RoHS; 名称: 二极管; 设备封装名称: SOD-323_1N4148; 贴片和直插: SMT
J15-J22 = 1.10.06.0009: as J5 on sheet 03. ZSN603
LED2 = 1.04.05.0002: as LED7 on sheet 03. ZSN603
Q2 = 1.04.09.0002: PNP Transistor; 名称: 三极管; 设备封装名称: SOT-23_SS8550LT; 厂商: 江苏长电; 贴片和直插: SMT
R10 = 1.01.01.0052: as R3 on sheet 03. ZSN603
R11 = 1.01.01.0037: as R2 on sheet 02. POWER
R12 = 1.01.01.0037: 1.5KΩ,0603,*,RoHS; 名称: 电阻; 设备封装名称: R0603_1.5K; 厂商: Ralec; 贴片和直插: SMT; 器件优选方案: 正常状态，可以选用

## Sheet 06. Analog Multiplexer.SchDoc
size A4; CheckedBy: 赵金生; Author: 伍伟业; CompanyName: 广州周立功单片机科技有限公司; DocumentNumber: 6; SheetNumber: 6; SheetTotal: 7; PageSetup: Record=PageOptions|CenterHorizontal=True|CenterVertical=True|PrintScale=1.00|XCorrection=1.00|YCorrection=1.00|PrintKind=0|BorderSize=5000000|LeftOffset=0|BottomOffset=0|Orientation=2|PaperLength=1000|PaperWidth=1000|Scale=100|PaperSource=7|PrintQuality=600|MediaType=1|DitherType=10|PaperKind=A4|PrintScaleMode=1; DesignDate: 2017-12-22; CheckDate: 2017-12-26; SheetName: Analog Multiplexer; SheetVersion: V1.01; SheetDescription: 模拟开关4051
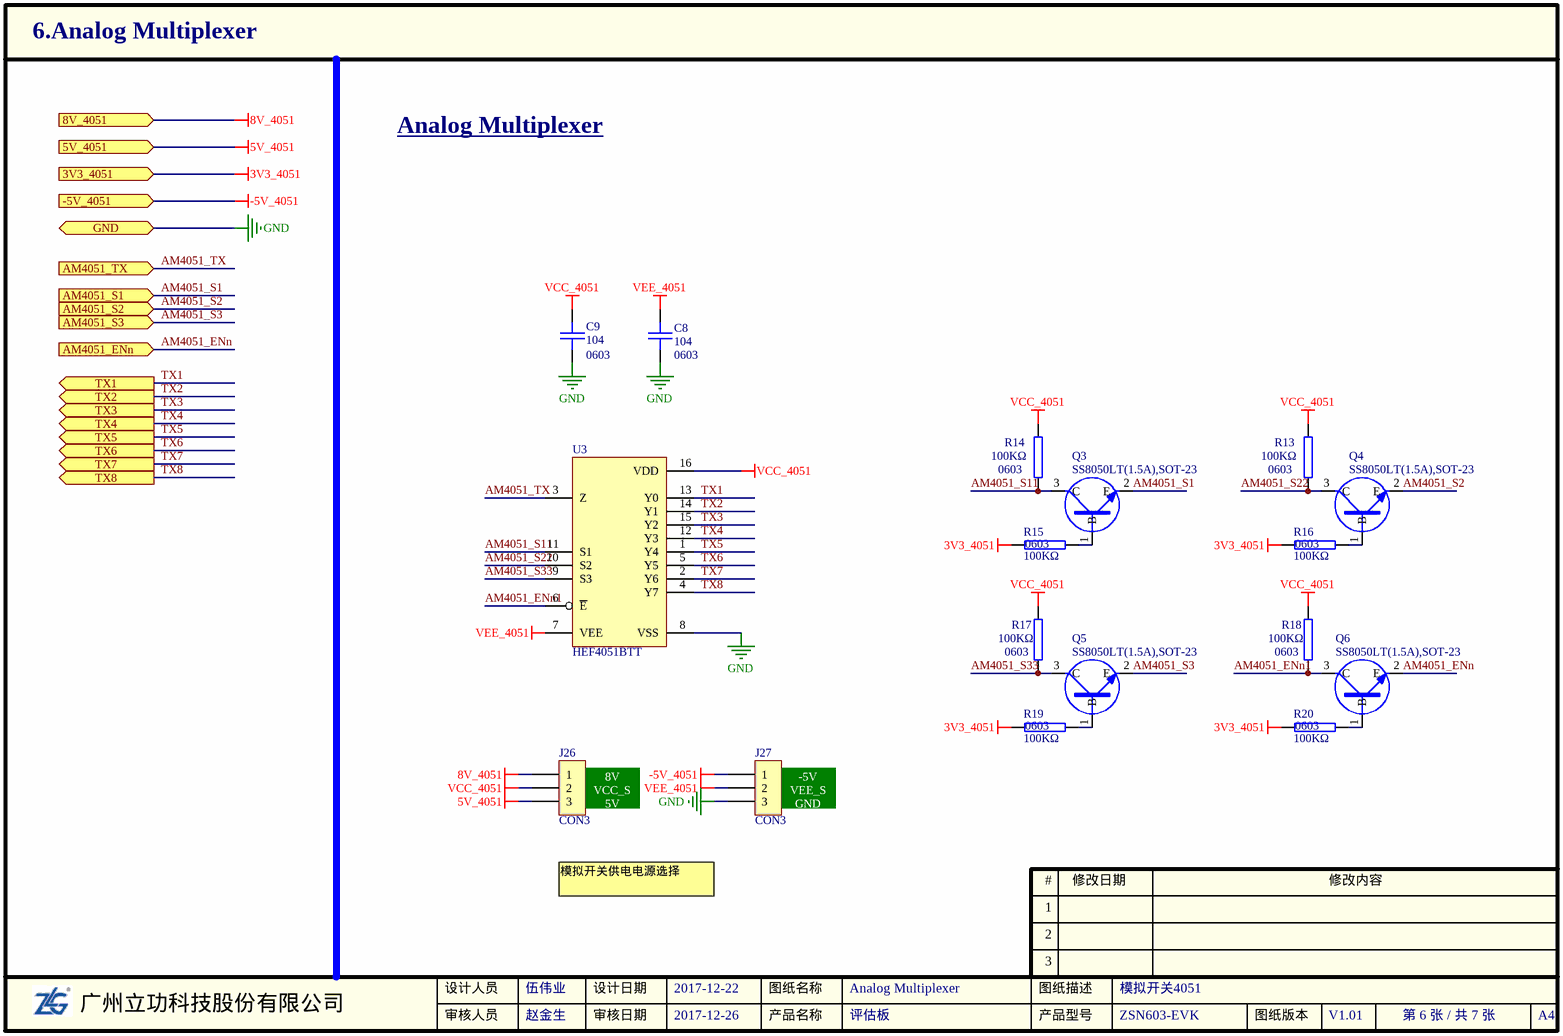
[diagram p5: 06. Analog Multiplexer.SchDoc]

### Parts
C8  封装: 0603  [0603C]  (hidden comment: 104)
C9  封装: 0603  [0603C]  (hidden comment: 104)
J26  CON3  [SIP-3-2.54]
J27  CON3  [SIP-3-2.54]
Q3  SS8050LT(1.5A),SOT-23  [SOT-23]
Q4  SS8050LT(1.5A),SOT-23  [SOT-23]
Q5  SS8050LT(1.5A),SOT-23  [SOT-23]
Q6  SS8050LT(1.5A),SOT-23  [SOT-23]
R13  封装: 0603  [0603R]  (hidden comment: 100KΩ)
R14  封装: 0603  [0603R]  (hidden comment: 100KΩ)
R15  封装: 0603  [0603R]  (hidden comment: 100KΩ)
R16  封装: 0603  [0603R]  (hidden comment: 100KΩ)
R17  封装: 0603  [0603R]  (hidden comment: 100KΩ)
R18  封装: 0603  [0603R]  (hidden comment: 100KΩ)
R19  封装: 0603  [0603R]  (hidden comment: 100KΩ)
R20  封装: 0603  [0603R]  (hidden comment: 100KΩ)
U3  HEF4051BTT  [SOP65P640X110-16N]

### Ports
3V3_4051 (in), 5V_4051 (in), 8V_4051 (in), -5V_4051 (in), AM4051_ENn (in), AM4051_S1 (in), AM4051_S2 (in), AM4051_S3 (in), AM4051_TX (in), GND, TX1 (out), TX2 (out), TX3 (out), TX4 (out), TX5 (out), TX6 (out), TX7 (out), TX8 (out)

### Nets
3V3_4051: R15.2 R16.2 R19.2 R20.2 ; port 3V3_4051  [project net 3.3V]
5V_4051: J26.3 ; port 5V_4051  [project net 5V]
8V_4051: J26.1 ; port 8V_4051  [project net 8V]
-5V_4051: J27.1 ; port -5V_4051  [project net -5V]
GND: C8.2 C9.2 J27.3 U3.8(VSS) ; port GND
VCC_4051: C9.1 J26.2 R13.2 R14.2 R17.2 R18.2 U3.16(VDD)
VEE_4051: C8.1 J27.2 U3.7(VEE)
AM4051_ENn: Q6.2(E) ; port AM4051_ENn
AM4051_ENn1: Q6.3(C) R18.1 U3.6(~{E})
AM4051_S1: Q3.2(E) ; port AM4051_S1
AM4051_S2: Q4.2(E) ; port AM4051_S2
AM4051_S3: Q5.2(E) ; port AM4051_S3
AM4051_S11: Q3.3(C) R14.1 U3.11(S1)
AM4051_S22: Q4.3(C) R13.1 U3.10(S2)
AM4051_S33: Q5.3(C) R17.1 U3.9(S3)
AM4051_TX: U3.3(Z) ; port AM4051_TX
TX1: U3.13(Y0) ; port TX1  [project net ANT1_TX]
TX2: U3.14(Y1) ; port TX2  [project net ANT2_TX]
TX3: U3.15(Y2) ; port TX3  [project net ANT3_TX]
TX4: U3.12(Y3) ; port TX4  [project net ANT4_TX]
TX5: U3.1(Y4) ; port TX5  [project net ANT5_TX]
TX6: U3.5(Y5) ; port TX6  [project net ANT6_TX]
TX7: U3.2(Y6) ; port TX7  [project net ANT7_TX]
TX8: U3.4(Y7) ; port TX8  [project net ANT8_TX]
NetQ3_1: Q3.1(B) R15.1
NetQ4_1: Q4.1(B) R16.1
NetQ5_1: Q5.1(B) R19.1
NetQ6_1: Q6.1(B) R20.1

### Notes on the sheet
- Analog Multiplexer
- (near J26) 8V
  VCC_S
  5V
- (near J27) -5V
  VEE_S
  GND
- 模拟开关供电电源选择

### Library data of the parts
C8 C9 = 1.02.01.0032: as C6 on sheet 03. ZSN603
J26 J27 = CON3: Connector
Q3-Q6 = 1.04.09.0001: SS8050LT(1.5A),SOT-23,长电,RoHS; 名称: 三极管; 设备封装名称: SOT-23_SS8050LT; 型号: SS8050LT(1.5A),SOT-23,江苏长电,RoHS; 贴片和直插: SMT; 器件优选方案: 正常状态，可以选用
R13-R20 = 1.01.01.0062: as R4 on sheet 03. ZSN603
U3 = 1.05.10.0716: HEF4051BTT,TSSOP16,Nexperia; 名称: 集成电路; 贴片和直插: SMT; PCB备注: 171228lmd; 器件优选方案: 正常状态，可以选用

## Sheet 07. PWR_ANT.SchDoc
size A4; CheckedBy: 赵金生; Author: 伍伟业; CompanyName: 广州周立功单片机科技有限公司; DocumentNumber: 7; SheetNumber: 7; SheetTotal: 7; PageSetup: Record=PageOptions¦CenterHorizontal=True¦CenterVertical=True¦PrintScale=1.00¦XCorrection=1.00¦YCorrection=1.00¦PrintKind=0¦BorderSize=5000000¦LeftOffset=0¦BottomOffset=0¦Orientation=2¦PaperLength=1000¦PaperWidth=1000¦Scale=100¦PaperSource=7¦PrintQuality=600¦MediaType=1¦DitherType=10¦PaperKind=A4¦PrintScaleMode=1; DesignDate: 2017-12-22; CheckDate: 2017-12-26; SheetName: PWR_ANT; SheetVersion: V1.01; SheetDescription: 升压、负电压电路
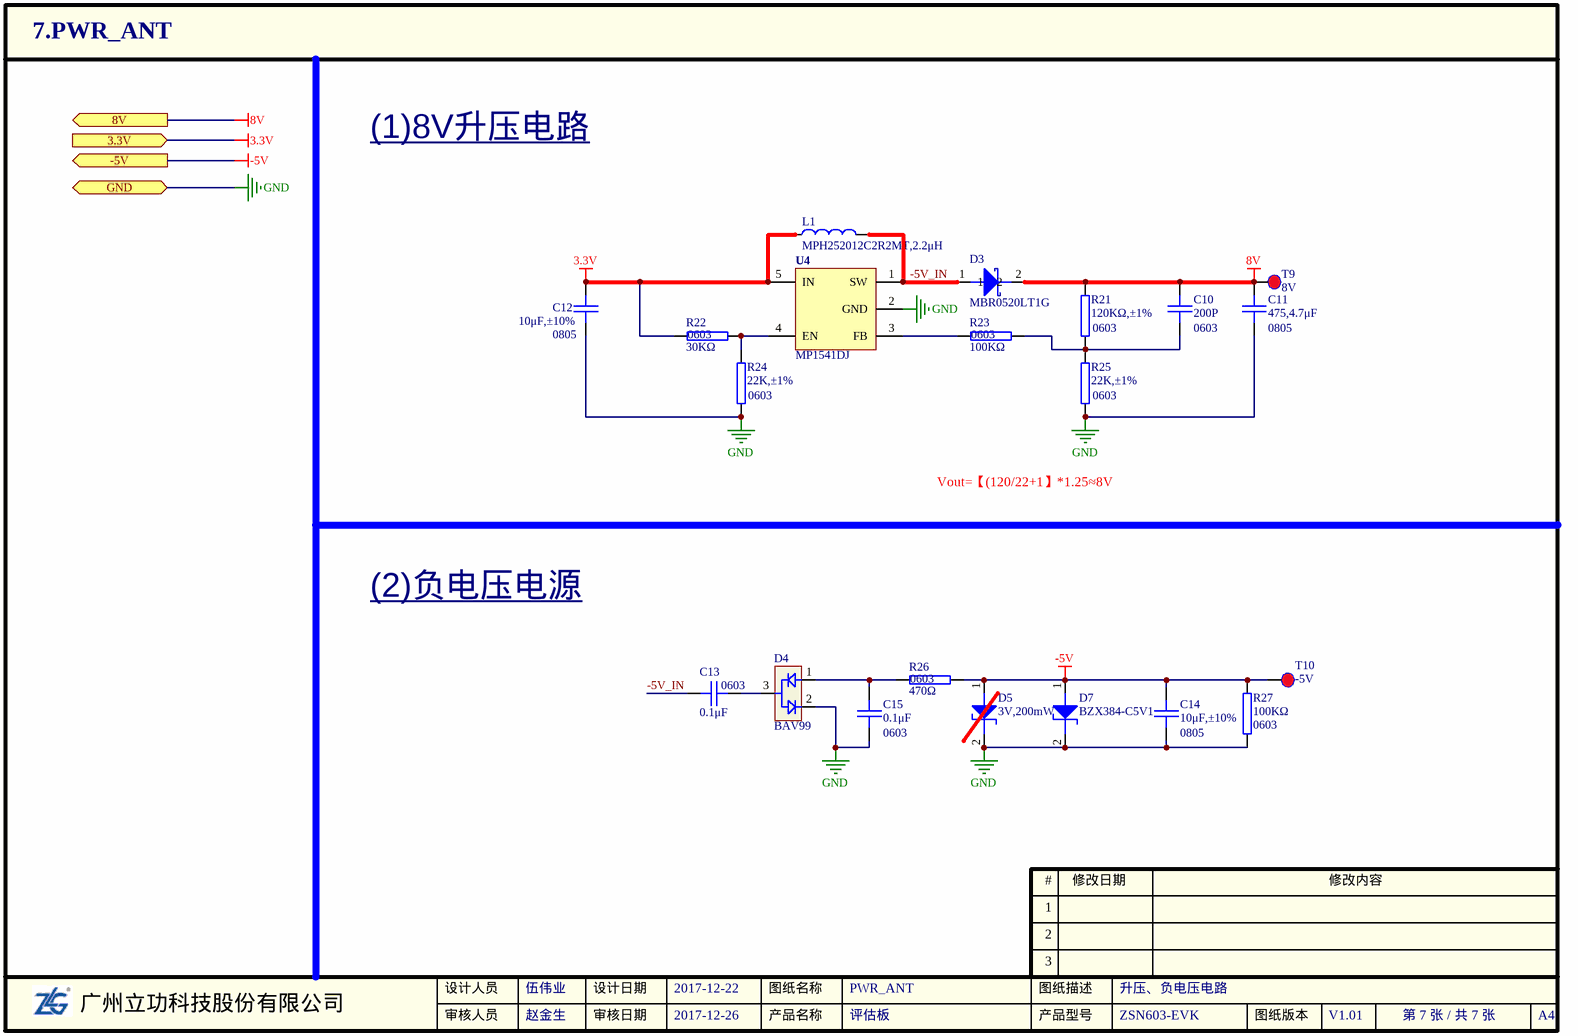
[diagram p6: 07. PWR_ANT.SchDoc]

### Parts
C10  封装: 0603  [0603C]  (hidden comment: 200P)
C11  封装: 0805  [0805C]  (hidden comment: 475,4.7μF)
C12  封装: 0805  [0805C]  (hidden comment: 10μF,±10%)
C13  封装: 0603  [0603C]  (hidden comment: 0.1μF)
C14  封装: 0805  [0805C]  (hidden comment: 10μF,±10%)
C15  封装: 0603  [0603C]  (hidden comment: 0.1μF)
D3  MBR0520LT1G  [SOD-123]
D4  BAV99  [SOT-23]
D5  3V,200mW  [SOD-123]
D7  BZX384-C5V1  [SOD-323]
L1  MPH252012C2R2MT,2.2μH  [INDC2520X10N]
R21  封装: 0603  [0603R]  (hidden comment: 120KΩ,±1%)
R22  封装: 0603  [0603R]  (hidden comment: 30KΩ)
R23  封装: 0603  [0603R]  (hidden comment: 100KΩ)
R24  封装: 0603  [0603R]  (hidden comment: 22K,±1%)
R25  封装: 0603  [0603R]  (hidden comment: 22K,±1%)
R26  封装: 0603  [0603R]  (hidden comment: 470Ω)
R27  封装: 0603  [0603R]  (hidden comment: 100KΩ)
T9  8V  [PAD-25/40]  (no BOM)
T10  -5V  [PAD-25/40]  (no BOM)
U4  MP1541DJ  [SOT-23-5]

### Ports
3.3V (in), 8V (out), -5V (out), GND

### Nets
3.3V: C12.1 L1.1 R22.2 U4.5(IN) ; port 3.3V
8V: C10.1 C11.1 D3.2 R21.2 T9.1 ; port 8V
-5V: C14.1 D5.1(A) D7.1(A) R26.2 R27.2 T10.1 ; port -5V
GND: C11.2 C12.2 C14.2 C15.1 D4.2(D2) D5.2(K) D7.2(K) R24.1 R25.1 R27.1 U4.2(GND) ; port GND
-5V_IN: C13.1 D3.1 L1.2 U4.1(SW)
NetC10_2: C10.2 R21.1 R23.1 R25.2
NetC13_2: C13.2 D4.3(A)
NetC15_2: C15.2 D4.1(D1) R26.1
NetR22_1: R22.1 R24.2 U4.4(EN)
NetR23_2: R23.2 U4.3(FB)

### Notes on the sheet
- (1)8V升压电路
- Vout=【(120/22+1】*1.25≈8V
- (2)负电压电源

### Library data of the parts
C10 = 1.02.01.0015: GRM1885C1H201JA01D,200P,±5%,50V,COG,0603,muRata,RoHS; 名称: 电容; 贴片和直插: SMT; 器件优选方案: 正常状态，可以选用; 设备封装名称: C0603_200P_COG_50V_5%
C11 = 1.02.02.0086: GRM21BR71C475KA73L,475,4.7μF,±10%,16V,X7R,0805,murata,RoHS; 名称: 电容; 贴片和直插: SMT; 器件优选方案: 正常状态，可以选用; PCB备注: 160216lmd
C12 C14 = 1.02.02.0117: 10μF,±10%,10V,X7R,GRM21BR71A106KE51L,0805,muRata,RoHS; 名称: 电容; 贴片和直插: SMT; 器件优选方案: 正常状态，可以选用; PCB备注: 171017lmd
C13 C15 = 1.02.01.0032: as C6 on sheet 03. ZSN603
D3 = 1.04.07.0014: MBR0520LT1G,SOD-123,ON,RoHS; 名称: 二极管; 设备封装名称: SOD-123_MBR0520; 贴片和直插: SMT; 器件优选方案: 正常状态，可以选用
D4 = 1.04.07.0010: BAV99,SOT-23,NXP,RoHS; 名称: 二极管; 设备封装名称: SOT-23_BAV99; 贴片和直插: SMT; 器件优选方案: 正常状态，可以选用
D5 = 1.04.01.0018: 3V,200mW,MMSZ4683,SOD-123,长电,RoHS; 名称: 稳压二极管; 设备封装名称: SOD-123_3V_200mW; 贴片和直插: SMT; 器件优选方案: 正常状态，可以选用
D7 = 04.03.00033: BZX384-C5V1,SOD-323,NEXPERIA,; 旧物料代码: 1.04.01.0017; 名称: 二极管; 贴片和直插: SMT; 器件优选方案: 通用物料
L1 = 1.03.01.0347: MPH252012C2R2MT,2.2μH,±20%,700mA,1008,Sunlord,RoHs; 名称: 电感; 贴片和直插: SMT; 器件优选方案: 正常状态，可以选用; 封装: 1008; PCB备注: 160722ZW   160729toPCB-hcj
R21 = 1.01.01.0064: 120KΩ,±1%,0603,*,RoHS; 名称: 电阻; 厂商: Ralec; 贴片和直插: SMT; 器件优选方案: 正常状态，可以选用; 设备封装名称: R0603_120K_1%
R22 = 1.01.01.0058: 30KΩ,0603,*,RoHS; 名称: 电阻; 设备封装名称: R0603_30K; 厂商: Ralec; 贴片和直插: SMT; 器件优选方案: 正常状态，可以选用
R23 R27 = 1.01.01.0062: as R4 on sheet 03. ZSN603
R24 R25 = 1.01.01.0152: 22K,±1%,0603,RoHS; 名称: 电阻; 厂商: Ralec; 贴片和直插: SMT; 器件优选方案: 正常状态，可以选用; 设备封装名称: R0603_22K_1%
R26 = 1.01.01.0032: 470Ω,0603,*,RoHS; 名称: 电阻; 设备封装名称: R0603_470R; 厂商: Ralec; 贴片和直插: SMT; 器件优选方案: 正常状态，可以选用
T9 T10 = TEST-DOT
U4 = 1.05.09.0258: MP1541DJ,TSOT23-5,MPS,RoHS; 名称: 集成电路; 贴片和直插: SMT; PCB备注: 151014mxz; 器件优选方案: 正常状态，可以选用

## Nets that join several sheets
3.3V: 02. POWER (5 pins), 03. ZSN603 (16 pins), 04. SAM (5 pins), 05. OTHERS (Q2.2 R10.2 R12.1), 06. Analog Multiplexer (R15.2 R16.2 R19.2 R20.2), 07. PWR_ANT (C12.1 L1.1 R22.2 U4.5)
5V: 02. POWER (10 pins), 03. ZSN603 (J9.1), 06. Analog Multiplexer (J26.3)
8V: 06. Analog Multiplexer (J26.1), 07. PWR_ANT (5 pins)
-5V: 06. Analog Multiplexer (J27.1), 07. PWR_ANT (6 pins)
GND: 02. POWER (18 pins), 03. ZSN603 (26 pins), 04. SAM (9 pins), 05. OTHERS (10 pins), 06. Analog Multiplexer (C8.2 C9.2 J27.3 U3.8), 07. PWR_ANT (11 pins)
AM4051_ENn: 03. ZSN603 (J2.7 U5.23), 06. Analog Multiplexer (Q6.2)
AM4051_S1: 03. ZSN603 (J2.4 U5.20), 06. Analog Multiplexer (Q3.2)
AM4051_S2: 03. ZSN603 (J2.5 U5.21), 06. Analog Multiplexer (Q4.2)
AM4051_S3: 03. ZSN603 (J2.6 U5.22), 06. Analog Multiplexer (Q5.2)
AM4051_TX: 03. ZSN603 (J8.2), 06. Analog Multiplexer (U3.3)
ANT1_TX: 05. OTHERS (J15.2), 06. Analog Multiplexer (U3.13)
ANT2_TX: 05. OTHERS (J16.2), 06. Analog Multiplexer (U3.14)
ANT3_TX: 05. OTHERS (J17.2), 06. Analog Multiplexer (U3.15)
ANT4_TX: 05. OTHERS (J18.2), 06. Analog Multiplexer (U3.12)
ANT5_TX: 05. OTHERS (J19.2), 06. Analog Multiplexer (U3.1)
ANT6_TX: 05. OTHERS (J20.2), 06. Analog Multiplexer (U3.5)
ANT7_TX: 05. OTHERS (J21.2), 06. Analog Multiplexer (U3.2)
ANT8_TX: 05. OTHERS (J22.2), 06. Analog Multiplexer (U3.4)
BEEP: 03. ZSN603 (J3.14 U5.3), 05. OTHERS (R11.1)
PA12/LED: 03. ZSN603 (J3.12 U5.5), 05. OTHERS (LED2.2)
PB3/SAM_RST: 03. ZSN603 (J3.6 U5.11), 04. SAM (5 pins)
PB4/SAM_CLK: 03. ZSN603 (J3.5 U5.12), 04. SAM (LED6.2 T7.1 U2.3 U6.6)
PB5/SAM_IO: 03. ZSN603 (J3.4 U5.13), 04. SAM (5 pins)
PB8/SAM_nPWR: 03. ZSN603 (J3.3 U5.14), 04. SAM (LED3.2 R9.1)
